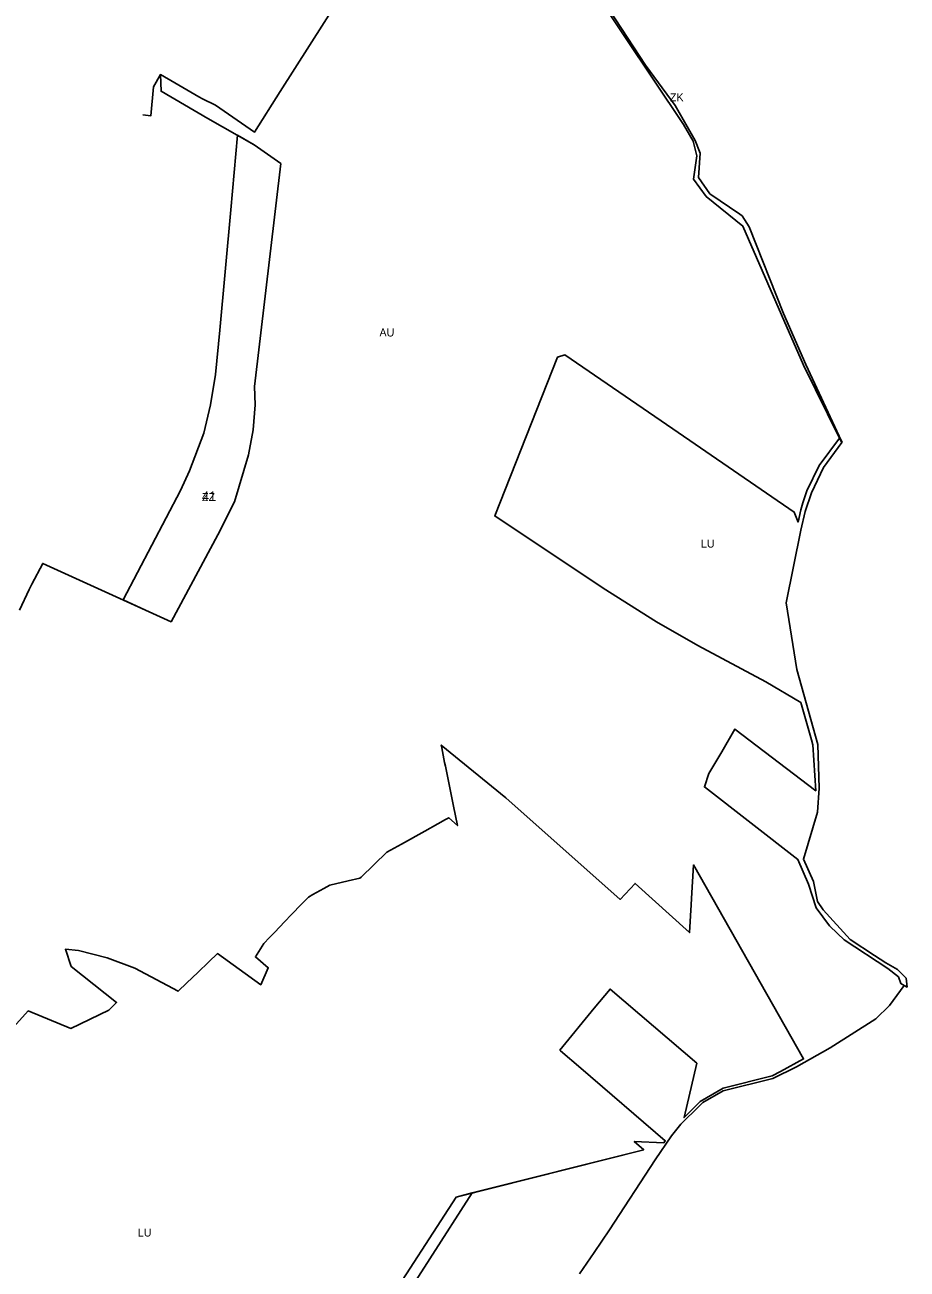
# Model space of a CAD drawing. Extents: x -541351 to -537540, y -1162694 to -1159725.
# Drawn here: x -538183 to -537632, y -1162094 to -1161316 of the extents above; entities that cross this region are included whole.
import ezdxf

# ---------------------------------------------------------------- set-up
doc = ezdxf.new("R2010")
doc.units = 0
for name, color, linetype in [('90670023', 7, 'Continuous'), ('90710013', 7, 'Continuous'), ('90750013', 7, 'Continuous'), ('90770013', 7, 'Continuous'), ('90910012', 7, 'Continuous'), ('ID_navrh', 7, 'Continuous')]:
    doc.layers.add(name, color=color, linetype=linetype)

msp = doc.modelspace()

# ---------------------------------------------------------------- linework, layer by layer
at = {"layer": '90670023'}
msp.add_lwpolyline([(-538091.738, -1161689.401), (-538107.66, -1161682.18), (-538121.681, -1161675.808), (-538085.722, -1161607.325), (-538080.155, -1161595.174), (-538071.276, -1161571.489), (-538067.109, -1161553.938), (-538063.944, -1161534.822), (-538061.329, -1161507.092), (-538054.412, -1161432.049), (-538050.204, -1161385.327), (-538039.72, -1161391.26), (-538023.13, -1161403.11), (-538039.578, -1161542.325), (-538039.196, -1161553.847), (-538040.511, -1161569.531), (-538043.27, -1161585.013), (-538052.027, -1161614.392), (-538062.434, -1161635.033)], close=True, dxfattribs=at)
at = {"layer": '90710013'}
msp.add_lwpolyline([(-537825.35, -1161295.54), (-537795.27, -1161341.6), (-537776.77, -1161366.86), (-537764.17, -1161388.68), (-537761.11, -1161396.65), (-537762.15, -1161411.84), (-537755.16, -1161421.95), (-537736.27, -1161434.72), (-537734.93, -1161435.64), (-537730.5, -1161442.66), (-537709.02, -1161496.84), (-537695, -1161528.73), (-537674.2, -1161573.51), (-537672.5, -1161577.12), (-537672.7, -1161577.39), (-537674.08, -1161574.59), (-537696.57, -1161528.99), (-537710.31, -1161497.52), (-537734.41, -1161442.14), (-537757.44, -1161423.63), (-537765.32, -1161412.85), (-537763.17, -1161398.15), (-537765.56, -1161389.07), (-537771.59, -1161378.63), (-537826.79, -1161296.05)], dxfattribs=at)
msp.add_lwpolyline([(-538134.96, -1162390.143), (-538134.96, -1162390.143), (-538140.901, -1162380.777), (-538140.901, -1162380.777), (-538116.81, -1162358.63), (-538081.87, -1162323), (-538041.52, -1162272.9), (-538020.92, -1162214.26), (-537980.73, -1162152.69), (-537959.1, -1162119.55), (-537913.59, -1162048.98), (-537903.511, -1162046.433), (-537956.408, -1162128.79), (-537995.859, -1162194.216), (-538005.857, -1162223.144), (-538008.924, -1162259.128), (-538108.15, -1162353.88)], close=True, dxfattribs=at)
at = {"layer": '90750013'}
for points in [[(-538186.37, -1161682.08), (-538180.3, -1161669.35), (-538178.66, -1161665.92), (-538171.84, -1161653.01), (-538107.66, -1161682.18), (-538091.738, -1161689.401), (-538062.434, -1161635.033), (-538052.027, -1161614.392), (-538043.27, -1161585.013), (-538040.511, -1161569.531), (-538039.196, -1161553.847), (-538039.578, -1161542.325), (-538023.13, -1161403.11), (-538039.72, -1161391.26), (-538068.79, -1161374.81), (-538097.93, -1161357.873), (-538098.33, -1161347.51), (-538089.39, -1161352.67), (-538074.35, -1161361.36), (-538072.11, -1161362.66), (-538063.88, -1161366.6), (-538039.54, -1161383.43), (-538023.45, -1161358.02), (-537986.93, -1161300.34)], [(-537826.79, -1161296.05), (-537771.59, -1161378.63), (-537765.56, -1161389.07), (-537763.17, -1161398.15), (-537765.32, -1161412.85), (-537757.44, -1161423.63), (-537734.41, -1161442.14), (-537710.31, -1161497.52), (-537696.57, -1161528.99), (-537674.08, -1161574.59), (-537686.87, -1161591.71), (-537694.5, -1161607.51), (-537696.89, -1161615.11), (-537698.29, -1161619.58), (-537699.93, -1161627.14), (-537702.37, -1161620.84), (-537778.16, -1161568.95), (-537845.61, -1161522.58), (-537850.3, -1161524.02), (-537889.44, -1161623.23), (-537821.78, -1161668.5), (-537788.35, -1161689.41), (-537762.49, -1161704.25), (-537720.04, -1161726.92), (-537698.17, -1161739.95), (-537691.59, -1161763.18), (-537690.68, -1161766.41), (-537688.95, -1161795.06), (-537739.44, -1161756.52), (-537747.56, -1161770.78), (-537750.68, -1161775.88), (-537755.79, -1161784.25), (-537758.48, -1161792.69), (-537700.05, -1161838.01), (-537693.46, -1161853.35), (-537688.55, -1161868.27), (-537680.33, -1161879.54), (-537675.39, -1161884.28), (-537671.25, -1161888.12), (-537643.95, -1161906.13), (-537637.28, -1161911.4), (-537635.7, -1161915.56), (-537633.76, -1161916.66), (-537642.83, -1161929.21), (-537651.4, -1161937.54), (-537679.87, -1161955.73), (-537700.91, -1161967.52), (-537715.69, -1161974.89), (-537746.83, -1161982.53), (-537759.37, -1161989.91), (-537761.46, -1161991.89), (-537773.2, -1162003.37), (-537778.94, -1162010.74), (-537789.26, -1162025.76), (-537817.83, -1162069.52), (-537827.3, -1162083.56), (-537836.59, -1162097.02)], [(-537956.408, -1162128.79), (-537903.511, -1162046.433), (-537796.39, -1162019.36), (-537802.31, -1162014.18), (-537783.76, -1162015.03), (-537782.94, -1162013.81), (-537835.7, -1161968.44), (-537848.3, -1161957.61), (-537848.8, -1161957.17), (-537827.34, -1161931.02), (-537817.45, -1161918.97), (-537763.12, -1161965.33), (-537771.22, -1161999.31), (-537761.1, -1161989.21), (-537746.83, -1161980.83), (-537716.17, -1161973.22), (-537710.98, -1161970.44), (-537696.51, -1161962.69), (-537765.19, -1161841.44), (-537766.56, -1161862.48), (-537766.78, -1161866.44), (-537767.71, -1161883.69), (-537801.8, -1161852.95), (-537811.01, -1161862.99), (-537882.54, -1161799.41), (-537922.87, -1161766.53), (-537922.53, -1161768.3), (-537920.77, -1161777.39), (-537920.34, -1161779.64), (-537918.82, -1161787.06), (-537915.24, -1161804.63), (-537912.77, -1161816.77), (-537918.1, -1161811.88), (-537920.21, -1161813.06), (-537924.94, -1161815.7), (-537933.13, -1161820.26), (-537947.8, -1161828.43), (-537956.93, -1161833.52), (-537972.84, -1161848.95), (-537973.7, -1161849.78), (-537981.13, -1161851.43), (-537992.56, -1161853.98), (-537996.3, -1161856.09), (-538003.18, -1161859.97), (-538005.94, -1161861.52), (-538010.24, -1161865.99), (-538016.49, -1161872.48), (-538020.76, -1161876.92), (-538026.97, -1161883.38), (-538030.27, -1161886.81), (-538033.84, -1161890.51), (-538038.96, -1161898.93), (-538031.03, -1161905.68), (-538035.67, -1161916.29), (-538062.65, -1161896.78), (-538068.12, -1161902.01), (-538074.96, -1161908.56), (-538081.8, -1161915.09), (-538087.35, -1161920.4), (-538114.45, -1161905.95), (-538131.71, -1161899.38), (-538149.46, -1161894.92), (-538157.77, -1161894.11), (-538154.17, -1161904.79), (-538125.74, -1161927.28), (-538130.55, -1161932.26), (-538154.41, -1161943.61), (-538181.01, -1161932.67), (-538241.75, -1162000)]]:
    msp.add_lwpolyline(points, dxfattribs=at)
at = {"layer": '90770013'}
msp.add_lwpolyline([(-537739.44, -1161756.52), (-537688.95, -1161795.06), (-537690.68, -1161766.41), (-537691.59, -1161763.18), (-537698.17, -1161739.95), (-537720.04, -1161726.92), (-537762.49, -1161704.25), (-537788.35, -1161689.41), (-537821.78, -1161668.5), (-537889.44, -1161623.23), (-537850.3, -1161524.02), (-537845.61, -1161522.58), (-537778.16, -1161568.95), (-537702.37, -1161620.84), (-537699.93, -1161627.14), (-537698.29, -1161619.58), (-537696.89, -1161615.11), (-537694.5, -1161607.51), (-537686.87, -1161591.71), (-537674.08, -1161574.59), (-537672.7, -1161577.39), (-537684.16, -1161592.93), (-537691.63, -1161608.81), (-537695.49, -1161620.49), (-537698.16, -1161632.19), (-537707.43, -1161677.5), (-537700.63, -1161719.2), (-537687.64, -1161766.24), (-537686.73, -1161793.4), (-537687.81, -1161808.36), (-537696.57, -1161837.73), (-537690.36, -1161851.82), (-537687.85, -1161864.33), (-537684.3, -1161869.41), (-537667.35, -1161887.98), (-537652.11, -1161898.02), (-537645.1, -1161902.57), (-537637.73, -1161906.76), (-537632.39, -1161912.23), (-537631.82, -1161917.75), (-537633.76, -1161916.66), (-537635.7, -1161915.56), (-537637.28, -1161911.4), (-537643.95, -1161906.13), (-537671.25, -1161888.12), (-537675.39, -1161884.28), (-537680.33, -1161879.54), (-537688.55, -1161868.27), (-537693.46, -1161853.35), (-537700.05, -1161838.01), (-537758.48, -1161792.69), (-537755.79, -1161784.25), (-537750.68, -1161775.88), (-537747.56, -1161770.78)], close=True, dxfattribs=at)
msp.add_lwpolyline([(-538241.75, -1162000), (-538181.01, -1161932.67), (-538154.41, -1161943.61), (-538130.55, -1161932.26), (-538125.74, -1161927.28), (-538154.17, -1161904.79), (-538157.77, -1161894.11), (-538149.46, -1161894.92), (-538131.71, -1161899.38), (-538114.45, -1161905.95), (-538087.35, -1161920.4), (-538081.8, -1161915.09), (-538074.96, -1161908.56), (-538068.12, -1161902.01), (-538062.65, -1161896.78), (-538035.67, -1161916.29), (-538031.03, -1161905.68), (-538038.96, -1161898.93), (-538033.84, -1161890.51), (-538030.27, -1161886.81), (-538026.97, -1161883.38), (-538020.76, -1161876.92), (-538016.49, -1161872.48), (-538010.24, -1161865.99), (-538005.94, -1161861.52), (-538003.18, -1161859.97), (-537996.3, -1161856.09), (-537992.56, -1161853.98), (-537981.13, -1161851.43), (-537973.7, -1161849.78), (-537972.84, -1161848.95), (-537956.93, -1161833.52), (-537947.8, -1161828.43), (-537933.13, -1161820.26), (-537924.94, -1161815.7), (-537920.21, -1161813.06), (-537918.1, -1161811.88), (-537912.77, -1161816.77), (-537915.24, -1161804.63), (-537918.82, -1161787.06), (-537920.34, -1161779.64), (-537920.77, -1161777.39), (-537922.53, -1161768.3), (-537922.87, -1161766.53), (-537882.54, -1161799.41), (-537811.01, -1161862.99), (-537801.8, -1161852.95), (-537767.71, -1161883.69), (-537766.78, -1161866.44), (-537766.56, -1161862.48), (-537765.19, -1161841.44), (-537696.51, -1161962.69), (-537710.98, -1161970.44), (-537716.17, -1161973.22), (-537746.83, -1161980.83), (-537761.1, -1161989.21), (-537771.22, -1161999.31), (-537763.12, -1161965.33), (-537817.45, -1161918.97), (-537827.34, -1161931.02), (-537848.8, -1161957.17), (-537848.3, -1161957.61), (-537835.7, -1161968.44), (-537782.94, -1162013.81), (-537783.76, -1162015.03), (-537802.31, -1162014.18), (-537796.39, -1162019.36), (-537913.59, -1162048.98), (-537959.1, -1162119.55)], dxfattribs=at)
at = {"layer": '90910012'}
msp.add_lwpolyline([(-538109.35, -1161372.69), (-538104.328, -1161373.143), (-538102.7, -1161355.1), (-538098.33, -1161347.51)], dxfattribs=at)

# ---------------------------------------------------------------- texts
at = {"layer": '90670023'}
msp.add_text('ZZ', height=5, rotation=360, dxfattribs=at).set_placement((-538072.405, -1161614.018))
at = {"layer": '90710013'}
msp.add_text('ZK', height=5, rotation=0, dxfattribs=at).set_placement((-537780.012, -1161364.15))
at = {"layer": '90750013'}
msp.add_text('AU', height=5, rotation=0, dxfattribs=at).set_placement((-537961.495, -1161511.143))
at = {"layer": '90770013'}
for p in [(-537760.63, -1161643.098), (-538112.461, -1162073.654)]:
    msp.add_text('LU', height=5, rotation=0, dxfattribs=at).set_placement(p)
at = {"layer": 'ID_navrh'}
msp.add_text('41', height=6, rotation=360, dxfattribs=at).set_placement((-538072.405, -1161614.018))

doc.saveas('drawing.dxf')
